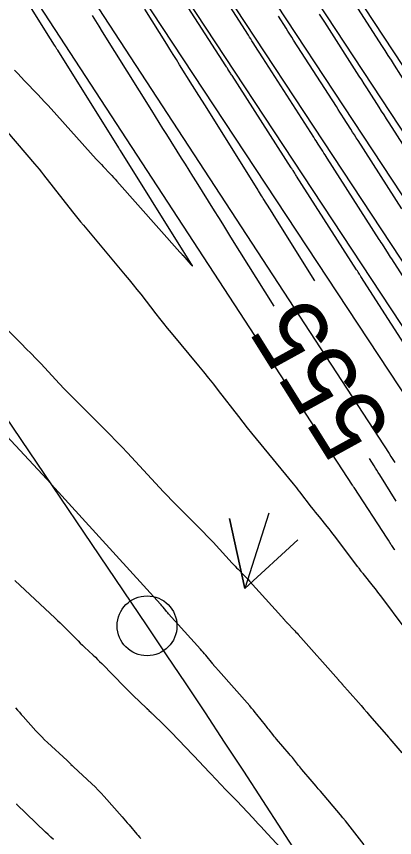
# Model space of a CAD drawing. Extents: x 954385 to 988206, y 1868364 to 1924553.
# Drawn here: x 957686 to 957717.7, y 1920041.8 to 1920110.4 of the extents above; entities that cross this region are included whole.
import ezdxf

# ---------------------------------------------------------------- set-up
doc = ezdxf.new("R2010")
doc.units = 0
for name, color, linetype in [('16', 7, 'Continuous'), ('21', 7, 'Continuous'), ('26', 7, 'Continuous'), ('5', 7, 'Continuous'), ('6', 7, 'Continuous'), ('7', 7, 'Continuous'), ('Default', 7, 'Continuous')]:
    doc.layers.add(name, color=color, linetype=linetype)

msp = doc.modelspace()

# ---------------------------------------------------------------- linework, layer by layer
at = {"layer": '16'}
for points in [[(957698.283, 1920136.745), (957732.756, 1920084.44)], [(957730.333, 1920082.664), (957695.897, 1920134.914)], [(957693.262, 1920133.461), (957727.911, 1920080.887)], [(957725.489, 1920079.111), (957690.628, 1920132.007)], [(957723.067, 1920077.335), (957687.993, 1920130.554)], [(957720.645, 1920075.559), (957685.358, 1920129.1)], [(957682.718, 1920126.67), (957717.191, 1920073.906), (957717.352, 1920073.659), (957717.513, 1920073.412), (957717.674, 1920073.166)], [(957717.675, 1920065.82), (957717.638, 1920065.877), (957717.411, 1920066.229), (957717.381, 1920066.275), (957717.132, 1920066.659), (957717.022, 1920066.828), (957714.26, 1920071.08), (957714.23, 1920071.126), (957714.2, 1920071.171), (957714.17, 1920071.217), (957714.14, 1920071.263), (957679.353, 1920124.508)], [(957677.043, 1920110.41), (957687.555, 1920098.121), (957687.748, 1920097.893), (957687.939, 1920097.662), (957688.127, 1920097.43), (957688.313, 1920097.195), (957690.738, 1920094.097), (957690.959, 1920093.817), (957691.182, 1920093.539), (957691.408, 1920093.263), (957691.635, 1920092.989), (957695.137, 1920088.81), (957695.465, 1920088.414), (957695.79, 1920088.015), (957696.112, 1920087.614), (957696.429, 1920087.209), (957697.692, 1920085.585), (957698.01, 1920085.18), (957698.33, 1920084.778), (957698.654, 1920084.379), (957698.981, 1920083.981), (957701.267, 1920081.228), (957701.685, 1920080.72), (957702.098, 1920080.209), (957702.507, 1920079.694), (957702.911, 1920079.176), (957704.593, 1920077), (957704.96, 1920076.529), (957705.33, 1920076.062), (957705.704, 1920075.597), (957706.082, 1920075.135), (957709.172, 1920071.381), (957709.308, 1920071.215), (957709.441, 1920071.048), (957709.574, 1920070.88), (957709.705, 1920070.711), (957710.692, 1920069.424), (957710.851, 1920069.219), (957711.011, 1920069.015), (957711.172, 1920068.812), (957711.335, 1920068.61), (957711.99, 1920067.805), (957712.153, 1920067.604), (957712.314, 1920067.4), (957712.474, 1920067.196), (957712.631, 1920066.99), (957714.536, 1920064.478), (957714.567, 1920064.438), (957714.597, 1920064.398), (957714.627, 1920064.358), (957714.657, 1920064.318), (957714.81, 1920064.117), (957714.824, 1920064.097), (957714.839, 1920064.078), (957714.854, 1920064.059), (957714.869, 1920064.04), (957714.93, 1920063.965), (957714.96, 1920063.927), (957714.99, 1920063.889), (957715.869, 1920062.789), (957716.02, 1920062.599), (957716.169, 1920062.408), (957716.317, 1920062.215), (957716.463, 1920062.021), (957718.51, 1920059.276)], [(957715.109, 1920041.194), (957713.947, 1920042.705), (957713.747, 1920042.963), (957713.543, 1920043.218), (957713.337, 1920043.47), (957713.128, 1920043.72), (957711.45, 1920045.696), (957711.277, 1920045.9), (957711.105, 1920046.103), (957710.931, 1920046.305), (957710.758, 1920046.508), (957709.899, 1920047.511), (957709.808, 1920047.618), (957709.719, 1920047.725), (957709.632, 1920047.834), (957709.545, 1920047.943), (957709.201, 1920048.384), (957709.114, 1920048.493), (957709.026, 1920048.602), (957708.937, 1920048.709), (957708.846, 1920048.815), (957707.777, 1920050.051), (957707.698, 1920050.144), (957707.62, 1920050.237), (957707.542, 1920050.332), (957707.466, 1920050.428), (957707.163, 1920050.812), (957707.088, 1920050.908), (957707.012, 1920051.004), (957706.936, 1920051.099), (957706.86, 1920051.195), (957706.143, 1920052.096), (957705.997, 1920052.277), (957705.849, 1920052.456), (957705.698, 1920052.634), (957705.545, 1920052.809), (957702.934, 1920055.769), (957702.897, 1920055.811), (957702.859, 1920055.853), (957702.822, 1920055.896), (957702.784, 1920055.938), (957702.582, 1920056.165), (957702.571, 1920056.178), (957702.56, 1920056.191), (957702.549, 1920056.205), (957702.538, 1920056.218), (957702.484, 1920056.285), (957702.451, 1920056.326), (957701.861, 1920057.054), (957701.758, 1920057.179), (957701.654, 1920057.303), (957701.548, 1920057.425), (957701.44, 1920057.546), (957698.763, 1920060.519), (957698.704, 1920060.585), (957698.647, 1920060.651), (957698.59, 1920060.718), (957698.533, 1920060.786), (957698.31, 1920061.058), (957698.254, 1920061.125), (957698.197, 1920061.192), (957698.139, 1920061.258), (957698.08, 1920061.324), (957688.977, 1920071.325), (957688.97, 1920071.332), (957688.939, 1920071.367), (957688.931, 1920071.375), (957682.191, 1920078.59)], [(957685.956, 1920052.648), (957686.119, 1920052.468), (957686.282, 1920052.287), (957686.445, 1920052.107), (957686.608, 1920051.926), (957687.674, 1920050.742), (957687.909, 1920050.487), (957688.15, 1920050.238), (957688.397, 1920049.995), (957688.649, 1920049.758), (957690.293, 1920048.25), (957690.32, 1920048.224), (957690.347, 1920048.198), (957690.373, 1920048.171), (957690.398, 1920048.143), (957690.5, 1920048.028), (957690.525, 1920048.001), (957690.549, 1920047.976), (957690.575, 1920047.95), (957690.601, 1920047.926), (957690.706, 1920047.828), (957690.732, 1920047.804), (957690.759, 1920047.78), (957690.785, 1920047.755), (957690.811, 1920047.731), (957692.355, 1920046.296), (957692.617, 1920046.045), (957692.873, 1920045.788), (957693.123, 1920045.525), (957693.365, 1920045.255), (957694.867, 1920043.54), (957695.014, 1920043.372), (957695.161, 1920043.204), (957695.307, 1920043.036), (957695.454, 1920042.868), (957696.113, 1920042.109), (957696.223, 1920041.984), (957696.337, 1920041.862), (957696.453, 1920041.743)]]:
    msp.add_lwpolyline(points, dxfattribs=at)
at = {"layer": '21'}
msp.add_circle((957696.959, 1920059.51), 2.5, dxfattribs=at)
at = {"layer": '26'}
msp.add_lwpolyline([(957707.131, 1920068.928), (957705.147, 1920062.629), (957703.846, 1920068.486), (957705.147, 1920062.629), (957709.569, 1920066.684)], dxfattribs=at)
at = {"layer": '6'}
for points in [[(957707.595, 1920086.214), (957703.976, 1920091.998), (957703.634, 1920092.544), (957703.292, 1920093.091), (957702.949, 1920093.637), (957702.607, 1920094.183), (957701.095, 1920096.598), (957700.784, 1920097.095), (957700.473, 1920097.592), (957700.161, 1920098.09), (957699.85, 1920098.587), (957698.604, 1920100.576), (957698.292, 1920101.074), (957697.981, 1920101.571), (957697.67, 1920102.068), (957697.358, 1920102.566), (957693.234, 1920109.157), (957692.953, 1920109.605), (957692.673, 1920110.053), (957692.392, 1920110.501)], [(957711.355, 1920110.617), (957711.571, 1920110.279), (957711.788, 1920109.941), (957714.673, 1920105.447), (957714.881, 1920105.123), (957715.09, 1920104.798), (957715.298, 1920104.473), (957715.506, 1920104.147), (957716.337, 1920102.847), (957716.545, 1920102.521), (957716.753, 1920102.196), (957716.961, 1920101.871), (957717.17, 1920101.546), (957720.151, 1920096.897)], [(957682.47, 1920086.987), (957686.457, 1920083.067), (957686.866, 1920082.661), (957687.271, 1920082.251), (957687.671, 1920081.837), (957688.068, 1920081.419), (957689.646, 1920079.74), (957690.043, 1920079.322), (957690.443, 1920078.907), (957690.846, 1920078.496), (957691.252, 1920078.087), (957693.386, 1920075.962), (957693.876, 1920075.47), (957694.36, 1920074.973), (957694.839, 1920074.472), (957695.314, 1920073.965), (957698.013, 1920071.056), (957698.34, 1920070.706), (957698.669, 1920070.36), (957699.002, 1920070.016), (957699.338, 1920069.676), (957701.135, 1920067.868), (957701.248, 1920067.754), (957701.362, 1920067.64), (957701.475, 1920067.525), (957701.588, 1920067.411), (957702.042, 1920066.953), (957702.154, 1920066.838), (957702.266, 1920066.722), (957702.377, 1920066.605), (957702.486, 1920066.487), (957704.087, 1920064.745), (957704.205, 1920064.618), (957704.324, 1920064.492), (957704.444, 1920064.367), (957704.565, 1920064.243), (957705.051, 1920063.748), (957705.172, 1920063.623), (957705.291, 1920063.498), (957705.41, 1920063.371), (957705.527, 1920063.243), (957708.206, 1920060.274), (957708.247, 1920060.229), (957708.287, 1920060.183), (957708.328, 1920060.138), (957708.369, 1920060.092), (957708.594, 1920059.838), (957708.603, 1920059.828), (957708.612, 1920059.818), (957708.621, 1920059.808), (957708.63, 1920059.799), (957708.677, 1920059.751), (957708.705, 1920059.722), (957709.228, 1920059.179), (957709.318, 1920059.084), (957709.407, 1920058.989), (957709.495, 1920058.893), (957709.582, 1920058.796), (957712.952, 1920055.002), (957712.977, 1920054.974), (957713.002, 1920054.946), (957713.027, 1920054.919), (957713.053, 1920054.892), (957713.155, 1920054.783), (957713.18, 1920054.756), (957713.205, 1920054.728), (957713.23, 1920054.701), (957713.255, 1920054.673), (957714.623, 1920053.109), (957714.859, 1920052.839), (957715.094, 1920052.569), (957715.33, 1920052.299), (957715.565, 1920052.028), (957717.18, 1920050.167), (957717.193, 1920050.151), (957717.207, 1920050.136), (957717.235, 1920050.106), (957717.242, 1920050.099), (957717.249, 1920050.091), (957717.256, 1920050.083), (957717.263, 1920050.076), (957718.271, 1920048.905)], [(957717.781, 1920069.93), (957716.406, 1920072.138), (957716.291, 1920072.323), (957716.176, 1920072.508), (957716.06, 1920072.692), (957715.945, 1920072.877), (957715.555, 1920073.5)]]:
    msp.add_lwpolyline(points, dxfattribs=at)
at = {"layer": '7'}
for points in [[(957685.882, 1920105.944), (957686.157, 1920105.648), (957686.435, 1920105.353), (957686.714, 1920105.06), (957687.836, 1920103.894), (957688.115, 1920103.601), (957688.392, 1920103.306), (957688.666, 1920103.009), (957688.938, 1920102.709), (957692.714, 1920098.512), (957692.855, 1920098.356), (957692.998, 1920098.201), (957693.141, 1920098.047), (957693.286, 1920097.894), (957693.866, 1920097.284), (957694.01, 1920097.13), (957694.153, 1920096.976), (957694.295, 1920096.82), (957694.436, 1920096.664), (957699.703, 1920090.734), (957699.722, 1920090.712), (957699.742, 1920090.69), (957699.763, 1920090.668), (957699.783, 1920090.646), (957699.864, 1920090.56), (957699.885, 1920090.538), (957699.905, 1920090.516), (957699.925, 1920090.494), (957699.944, 1920090.472), (957700.631, 1920089.694), (957700.725, 1920089.594), (957700.764, 1920089.566), (957700.749, 1920089.611), (957700.679, 1920089.73), (957699.984, 1920090.841), (957699.927, 1920090.933), (957694.739, 1920099.216), (957694.667, 1920099.33), (957694.596, 1920099.444), (957689.492, 1920107.599), (957689.426, 1920107.706), (957689.359, 1920107.812), (957689.293, 1920107.919), (957689.226, 1920108.025), (957688.892, 1920108.557), (957688.693, 1920108.877), (957684.243, 1920115.982)], [(957721.842, 1920083.274), (957717.409, 1920090.18), (957717.322, 1920090.315), (957717.235, 1920090.45), (957717.149, 1920090.585), (957717.062, 1920090.72), (957716.717, 1920091.26), (957716.63, 1920091.395), (957716.544, 1920091.53), (957716.457, 1920091.665), (957716.371, 1920091.8), (957712.024, 1920098.578), (957711.93, 1920098.724), (957711.837, 1920098.871), (957711.743, 1920099.017), (957711.65, 1920099.163), (957711.276, 1920099.747), (957711.182, 1920099.894), (957711.089, 1920100.04), (957710.995, 1920100.186), (957710.901, 1920100.332), (957706.637, 1920106.975), (957706.536, 1920107.132), (957706.435, 1920107.29), (957706.335, 1920107.447), (957706.234, 1920107.604), (957705.831, 1920108.234), (957705.731, 1920108.391), (957705.63, 1920108.549), (957705.529, 1920108.706), (957705.428, 1920108.863), (957701.251, 1920115.372)], [(957719.947, 1920080.734), (957714.837, 1920088.694), (957714.808, 1920088.741), (957714.778, 1920088.787), (957714.748, 1920088.834), (957714.718, 1920088.88), (957714.599, 1920089.066), (957714.54, 1920089.159), (957714.48, 1920089.251), (957709.451, 1920097.094), (957709.414, 1920097.151), (957709.378, 1920097.208), (957709.342, 1920097.264), (957709.306, 1920097.321), (957709.161, 1920097.548), (957709.125, 1920097.604), (957709.088, 1920097.661), (957709.052, 1920097.717), (957709.016, 1920097.774), (957704.061, 1920105.492), (957704.019, 1920105.559), (957703.976, 1920105.626), (957703.933, 1920105.693), (957703.89, 1920105.76), (957703.719, 1920106.028), (957703.676, 1920106.095), (957703.633, 1920106.162), (957703.59, 1920106.229), (957703.547, 1920106.296), (957698.673, 1920113.89)], [(957714.364, 1920111.425), (957716.559, 1920108.005), (957716.824, 1920107.591), (957717.09, 1920107.176), (957717.355, 1920106.762), (957717.621, 1920106.347), (957718.681, 1920104.688)], [(957710.983, 1920088.335), (957707.723, 1920093.545), (957707.499, 1920093.902), (957707.276, 1920094.259), (957706.677, 1920095.216), (957706.605, 1920095.332), (957706.532, 1920095.448), (957706.278, 1920095.854), (957706.241, 1920095.912), (957701.833, 1920102.952), (957701.294, 1920103.812), (957700.756, 1920104.672), (957699.679, 1920106.391), (957699.41, 1920106.821), (957699.141, 1920107.251), (957698.872, 1920107.681), (957698.603, 1920108.111), (957696.774, 1920111.033)], [(957718.261, 1920094.349), (957714.597, 1920100.062), (957714.446, 1920100.298), (957714.295, 1920100.533), (957714.144, 1920100.769), (957713.993, 1920101.005), (957713.391, 1920101.947), (957713.24, 1920102.183), (957713.089, 1920102.419), (957712.938, 1920102.654), (957712.787, 1920102.89), (957709.213, 1920108.458), (957709.054, 1920108.706), (957708.895, 1920108.953), (957708.736, 1920109.201), (957708.578, 1920109.449), (957707.944, 1920110.44)], [(957685.912, 1920063.298), (957689.27, 1920060.159), (957689.486, 1920059.955), (957689.7, 1920059.749), (957689.912, 1920059.542), (957690.122, 1920059.332), (957691.027, 1920058.418), (957691.202, 1920058.243), (957691.379, 1920058.069), (957691.557, 1920057.897), (957691.736, 1920057.727), (957692.457, 1920057.048), (957692.637, 1920056.877), (957692.814, 1920056.705), (957692.99, 1920056.531), (957693.165, 1920056.355), (957695.067, 1920054.418), (957695.251, 1920054.232), (957695.436, 1920054.048), (957695.623, 1920053.866), (957695.812, 1920053.686), (957696.914, 1920052.641), (957696.931, 1920052.624), (957696.948, 1920052.608), (957696.965, 1920052.592), (957696.982, 1920052.576), (957697.049, 1920052.51), (957697.066, 1920052.494), (957697.082, 1920052.477), (957697.099, 1920052.461), (957697.115, 1920052.444), (957697.295, 1920052.26), (957697.33, 1920052.224), (957697.366, 1920052.189), (957697.402, 1920052.153), (957697.438, 1920052.118), (957698.331, 1920051.258), (957698.491, 1920051.103), (957698.65, 1920050.945), (957698.806, 1920050.786), (957698.962, 1920050.626), (957701.4, 1920048.076), (957701.624, 1920047.841), (957701.848, 1920047.605), (957702.072, 1920047.369), (957702.295, 1920047.133), (957703.539, 1920045.812), (957703.586, 1920045.763), (957703.633, 1920045.714), (957703.681, 1920045.665), (957703.73, 1920045.617), (957703.931, 1920045.419), (957703.976, 1920045.375), (957704.021, 1920045.33), (957704.066, 1920045.286), (957704.111, 1920045.242), (957704.29, 1920045.064), (957704.335, 1920045.02), (957704.379, 1920044.975), (957704.423, 1920044.929), (957704.466, 1920044.883), (957705.791, 1920043.463), (957706.026, 1920043.211), (957706.261, 1920042.959), (957706.495, 1920042.706), (957706.73, 1920042.453), (957710.479, 1920038.405)], [(957689.135, 1920041.66), (957688.916, 1920041.862), (957688.698, 1920042.066), (957688.482, 1920042.272), (957686.083, 1920044.582), (957686.059, 1920044.605), (957686.034, 1920044.628)]]:
    msp.add_lwpolyline(points, dxfattribs=at)
at = {"layer": 'Default'}
msp.add_line((957696.959, 1920059.51), (957504.115, 1920344.606), dxfattribs=at)
msp.add_arc((956871.597, 1919501.221), 996.448, 12.648055, 34.075074, dxfattribs=at)

# ---------------------------------------------------------------- texts
at = {"layer": '5'}
msp.add_text('555', height=6, rotation=122.05009, dxfattribs=at).set_placement((957717.529, 1920076))

doc.saveas('drawing.dxf')
